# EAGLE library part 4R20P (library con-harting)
CONNECTOR
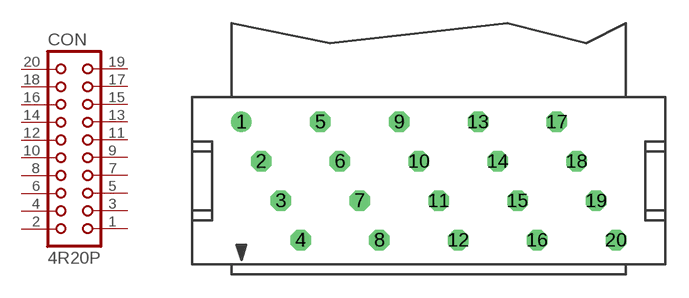
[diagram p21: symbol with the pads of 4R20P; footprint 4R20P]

Designator prefix CON

## 4R20P (OC_FARNELL: unknown; OC_NEWARK: unknown)  [4R20P]
1  1  pas
2  2  pas
3  3  pas
4  4  pas
5  5  pas
6  6  pas
7  7  pas
8  8  pas
9  9  pas
10  10  pas
11  11  pas
12  12  pas
13  13  pas
14  14  pas
15  15  pas
16  16  pas
17  17  pas
18  18  pas
19  19  pas
20  20  pas

## Footprint 4R20P (pad centres in mm)
CONNECTOR
drill 0.813 round: 1 -12.065,3.81
drill 0.813 octagon: 2 -10.795,1.27; 3 -9.525,-1.27; 4 -8.255,-3.81; 5 -6.985,3.81; 6 -5.715,1.27; 7 -4.445,-1.27; 8 -3.175,-3.81; 9 -1.905,3.81; 10 -0.635,1.27; 11 0.635,-1.27; 12 1.905,-3.81; 13 3.175,3.81; 14 4.445,1.27; 15 5.715,-1.27; 16 6.985,-3.81; 17 8.255,3.81; 18 9.525,1.27; 19 10.795,-1.27; 20 12.065,-3.81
